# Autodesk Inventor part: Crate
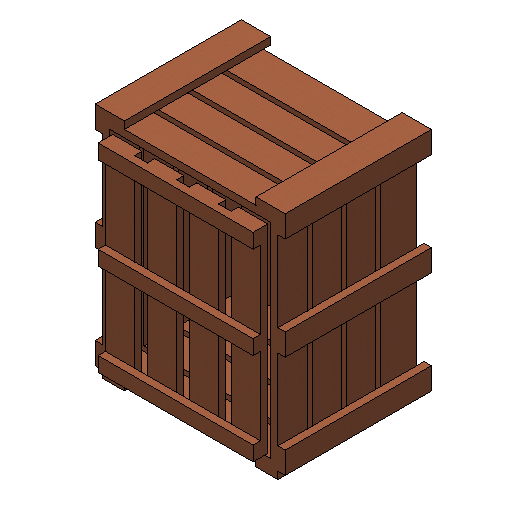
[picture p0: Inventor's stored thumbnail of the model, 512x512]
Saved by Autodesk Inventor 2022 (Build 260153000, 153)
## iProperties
RuleStatus: InUse
Created: 2009-11
Part Number: Crate
Document SubType Name: Modeling
Designer: Autodesk, Inc.
Density: 1 g/cm^3
Material: 一般
Appearance: ホワイト オーク材 - 硬質 塗装 淡い色 光沢なし
Key Parameters: Length=1500.000 mm;Width=1200.000 mm;Height=1000.000 mm;Angle=0.00 deg;
Author: Autodesk, Inc.
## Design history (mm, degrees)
sketch "Sketch1"
  geometry: L1 (0, 0)-(1200, 0); L2 (1200, 0)-(1200, 1500); L3 (1200, 1500)-(0, 1500); L4 (0, 1500)-(0, 0); L5 (0, 0)-(50, 50); L6 (1200, 1500)-(1150, 1450); L7 (50, 50)-(1150, 50); L8 (1150, 50)-(1150, 1450); L9 (1150, 1450)-(50, 1450); L10 (50, 1450)-(50, 50)
  constraints: 20 end point, 4 parallel, 2 horizontal, 2 perpendicular
  dimensions: "d0" = 1500 distance of L3.end L1.start (derived); "d1" = 1200 distance of L1.start L1.end (derived); "d2" = 50 horizontal distance of L1.start L5.end (= Thickness); "d3" = 50 horizontal distance of L1.start L5.end (= Thickness); "d5" = 50 horizontal distance of L2.end L6.end (= Thickness); "d6" = 50 horizontal distance of L2.end L6.end (= Thickness)
extrude "Extrusion1" new body sketch "Sketch1" distance "d7" = 200; taper "d8" = 0 deg
pattern_linear "Rectangular Pattern1" dims "d9" = 38 (derived), "d11" = 700 (derived)
sketch "Sketch2"
  geometry: L1 (-200, 0)-(800, 0); L2 (800, 0)-(800, 150); L3 (800, 150)-(-200, 150); L4 (-200, 150)-(-200, 0)
  constraints: 8 end point, 2 parallel, 1 horizontal, 1 perpendicular
  dimensions: "d12" = 150 distance of L3.end L1.start; "d13" = 1000 distance of L1.start L1.end (derived)
extrude "Extrusion2" join sketch "Sketch2" distance "d14" = 50 (= Thickness); taper "d15" = 0 deg
pattern_linear "Rectangular Pattern2" dims "d18" = 1400 (derived)
sketch "Sketch4"
  geometry: L1 (1250, 200)-(0, 200) reference; L2 (0, 0)-(0, 200) reference; L3 (0, 0)-(1200, 0) reference; L4 (1200, 0)-(1200, -33.333) reference; L5 (1200, -33.333)-(0, -33.333) reference; L6 (0, -233.333)-(0, -33.333) reference; L7 (0, -233.333)-(1200, -233.333) reference; L8 (1200, -233.333)-(1200, -266.667) reference; L9 (1200, -800)-(1250, -800) reference; L10 (1250, -800)-(1250, 200) reference; L11 (1200, 200)-(1050, 200); L12 (1050, 200)-(1050, -800); L13 (1050, -800)-(1200, -800); L14 (1200, -800)-(1200, 200); L15 (1200, -266.667)-(0, -266.667) reference; L16 (0, -466.667)-(0, -266.667) reference; L17 (0, -466.667)-(1200, -466.667) reference; L18 (1200, -466.667)-(1200, -500) reference; L19 (1200, -500)-(0, -500) reference; L20 (0, -700)-(0, -500) reference; L21 (0, -700)-(1200, -700) reference; L22 (1200, -700)-(1200, -800) reference
  constraints: 8 end point, 2 parallel, 1 horizontal, 1 perpendicular
  dimensions: "d19" = 1000 distance of L13.end L11.start (derived); "d20" = 150 distance of L12.end L13.end
extrude "Extrusion3" join sketch "Sketch4" distance "d21" = 50 (= Thickness); taper "d22" = 0 deg
pattern_linear "Rectangular Pattern3" dims "d23" = 24 (= BoardNumbersWidth1), "d25" = 1050 (derived)
workplane "Work Plane3"
workplane "Work Plane4"
mirror "Mirror1"
mirror "Mirror2"
workplane "Work Plane5"
  workaxis "Work Axis1"
workplane "Work Plane7"
sketch "Sketch18"
  geometry: L1 (0, 0)-(0, -150) reference; L2 (50, -150)-(0, -150) reference; L3 (50, -150)-(50, 0) reference; L4 (50, 0)-(0, 0) reference; L5 (1100, 1400)-(1300, 1400) reference; L6 (1100, 1350)-(1100, 1400) reference; L7 (1250, 1350)-(1100, 1350) reference; L8 (50, -200)-(200, -200) reference; L9 (200, -150)-(200, -200) reference; L10 (200, -150)-(50, -150) reference; L11 (50, -150)-(50, -200) reference; L12 (50, -150)-(1250, -150); L13 (1250, -150)-(1250, 1350); L14 (1250, 1350)-(50, 1350); L15 (50, 1350)-(50, -150); L16 (50, -150)-(1250, 1350); L17 (50, 1350)-(1250, -150); L18 (1250, 1250)-(1250, 1350) reference; L19 (1250, 1250)-(1300, 1250) reference; L20 (1300, 1400)-(1300, 1250) reference; 2 further points
  constraints: 12 end point, 2 parallel, 1 horizontal, 1 midpoint, 1 perpendicular
  node "Projected Loop11"
  node "Projected Loop12"
workpoint "Work Point2"
node "Landing Surface"
node "Insertion Point1"
body "Solid1"
sketch "Sketch12"
  geometry: L1 (0, 0)-(1200, 0); L2 (1200, 0)-(1200, 1500); L3 (1200, 1500)-(0, 1500); L4 (0, 1500)-(0, 0)
  constraints: 8 end point, 2 parallel, 1 horizontal, 1 perpendicular
  dimensions: "d66" = 1500 distance of L1.end L2.end (derived); "d67" = 1200 distance of L2.end L3.end (derived)
extrude "Extrusion4" join sketch "Sketch12" distance "d68" = 50 (= Thickness); taper "d69" = 0 deg
sketch "Sketch16"
  geometry: L1 (0, 0)-(-20, 20); L2 (-20, 20)-(-1380, 20); L3 (-1380, 20)-(-1380, 220); L4 (-1380, 220)-(-20, 220); L5 (-20, 220)-(-20, 20); 1 further point
  constraints: 10 end point, 2 parallel, 1 horizontal, 1 perpendicular
  dimensions: "d90" = 20 horizontal distance of L1.start L1.end; "d91" = 20 horizontal distance of L1.start L1.end; "d92" = 200 distance of L2.end L3.end; "d93" = 1360 distance of L3.end L4.end (derived)
extrude "Extrusion5" join sketch "Sketch16" distance "d94" = 50 (derived); taper "d95" = 0 deg
pattern_linear "Rectangular Pattern4" dims "d96" = 42.4 (derived), "d98" = 860 (derived)
sketch "Sketch17"
  geometry: L1 (20, 20)-(1080, 20); L2 (1080, 20)-(1080, 120); L3 (1080, 120)-(20, 120); L4 (20, 120)-(20, 20); 1 further point
  constraints: 8 end point, 2 parallel, 1 horizontal, 1 perpendicular
  dimensions: "d99" = 100 distance of L3.end L1.start; "d100" = 1060 distance of L2.end L3.end (derived)
extrude "Extrusion6" join sketch "Sketch17" distance "d101" = 50 (derived); taper "d102" = 0 deg
pattern_linear "Rectangular Pattern5" dims "d103" = 27.2 (derived), "d105" = 1260 (derived)
node "Projected Loop1"
other parameters: "Thickness" = 50 [user parameter; used in 7 equation terms], "BoardsNumbers" = 38 [user parameter; used in 2 equation terms], "BoardsNumbers1" = 38 (= BoardsNumbers) [user parameter], "BoardNumbersWidth" = 24 [user parameter; used in 2 equation terms], "BoardNumbersWidth1" = 24 (= BoardNumbersWidth) [user parameter; used in 1 equation term], "d32" = 0 (derived), "RoofNumbersWidth" = 42.4 [user parameter; used in 2 equation terms], "RoofNumbersWidth1" = 42.4 (= RoofNumbersWidth) [user parameter], "RoofNumbersLength" = 27.2 [user parameter; used in 2 equation terms], "RoofNumbersLength1" = 27.2 (= RoofNumbersLength) [user parameter]
